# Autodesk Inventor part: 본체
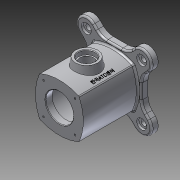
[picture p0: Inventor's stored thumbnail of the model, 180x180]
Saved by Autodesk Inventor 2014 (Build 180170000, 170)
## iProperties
Created: 2016-05
Part Number: 본체
Material: 알루미늄 6061
Document SubType Name: Modeling
Designer: Administrator
Density: 2.71 g/cm^3
Appearance: 알루미늄 - 평지
Mass: 1114.31 g
Surface Area: 867.27 cm^2
Volume: 411.184 cm^3
Author: Administrator
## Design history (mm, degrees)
sketch "스케치2"
  geometry: L1 (-35.355, -35.355)-(35.355, -35.355); L2 (35.355, -35.355)-(35.355, 35.355); L3 (35.355, 35.355)-(-35.355, 35.355); L4 (-35.355, 35.355)-(-35.355, -35.355); L5 (-35.355, -35.355)-(35.355, 35.355); L6 (35.355, -35.355)-(-35.355, 35.355); L7 (0, -60.2)-(0, 60.2) reference; A1 r 85.579 centre (42.579, 0) between (-35.355, 35.355) and (-35.355, -35.355); A2 r 85.579 centre (0, 42.579) between (-35.355, -35.355) and (35.355, -35.355); A3 r 85.579 centre (-42.579, 0) between (35.355, -35.355) and (35.355, 35.355); A4 r 85.579 centre (0, -42.579) between (35.355, 35.355) and (-35.355, 35.355); 5 further points
  constraints: 12 end point, 12 point on circle, 4 centre point, 2 equal radius, 2 midpoint, 2 parallel, 1 horizontal, 1 perpendicular
  dimensions: "d4" = 100 distance of L1.end L3.end; "d5" = 45 deg angle of L7 L6; "d6" = 86 distance of point (0, -43) point (0, 43); "d7" = 86 distance of point (43, 0) point (-43, 0)
extrude "돌출1" new body sketch "스케치2" distance "d8" = 55; taper "d9" = 0 deg
sketch "스케치3"
  geometry: 2 further points
  constraints: 1 coincident
hole "구멍1" sketch "스케치3" at (0, 0) diameter "d10" = 50; stored, may be unused: countersink angle "d14" = 90 deg, drill point angle "d16" = 118 deg; dims "d11" = 6, "d12" = 70, "d13" = 43, "d15" = 8
sketch "스케치5"
  geometry: L1 (49, 55)-(49, 39); L2 (49, 39)-(71.821, 39); L3 (71.821, 39)-(69, 55); L4 (69, 55)-(49, 55); L5 (-22, 0)-(132, 0) reference; L6 (0, 43)-(110, 43) reference; L7 (0, -35.355)-(0, 35.355) reference; 1 further point
  constraints: 8 end point, 1 parallel, 1 perpendicular, 1 vertical
  dimensions: "d22" = 39 distance between parallel lines of L5 L2; "d23" = 55 distance between parallel lines of L5 L4; "d24" = 100 deg angle of L6 L3; "d25" = 49 distance between parallel lines of L7 L1; "d26" = 20 distance of L3.end L1.start
revolve "회전1" sketch "스케치5" stored, may be unused: angle "d27" = 90 deg
hole "구멍2" diameter "d30" = 25; stored, may be unused: countersink angle "d34" = 90 deg, drill point angle "d36" = 0 deg; dims "d28" = 10, "d29" = 10, "d31" = 6, "d32" = 30, "d33" = 8, "d35" = 8
sketch "스케치6" dims "d43" = 70
  geometry: L1 (0, 42.579)-(-49, 42.579); L2 (-49, 42.579)-(-49, 91.579); L3 (-49, 91.579)-(0, 91.579); L4 (0, 91.579)-(0, 42.579); L5 (0, 42.579)-(-67.637, 110.215); L6 (-74.953, 92.076)-(-49.497, 117.532); L7 (-49.497, 117.532)-(-23.544, 91.579); L8 (-23.544, 91.579)-(-49, 66.123); L9 (-49, 66.123)-(-74.953, 92.076); A1 r 25 centre (0, 42.579) between (0, 67.579) and (-25, 42.579) reference; 2 further points
  constraints: 18 end point, 5 point on line, 4 parallel, 3 perpendicular, 2 point on circle, 1 coincident, 1 horizontal, 3 other
  dimensions: "d37" = 45 deg angle of L4 L5; "d38" = 98 diameter of L2 L4; "d40" = 36 distance of L6.start L6.end; "d41" = 18 distance between parallel lines of L5 L7; "d44" = 18 distance from line of L6 point (-49.497, 92.076)
extrude "돌출4" join sketch "스케치6" distance "d47" = 12; taper "d48" = 0 deg
fillet "모깎기1"
fillet "모깎기2" dims "d49" = 25
hole "구멍3" diameter "d52" = 10; stored, may be unused: countersink angle "d56" = 90 deg, drill point angle "d58" = 0 deg; dims "d50" = 10, "d51" = 10, "d53" = 6, "d54" = 18, "d55" = 4, "d57" = 8
sketch "스케치7" dims "d60" = 40
  geometry: L1 (-30.866, 13.744)-(-36.77, 19.647) reference; L2 (0, -42.579)-(-49.497, 6.919); C1 r 25 at (0, -42.579) reference; A1 r 18 centre (-49.497, 6.919) between (-36.77, 19.647) and (-62.225, -5.809) reference; 1 further point
  constraints: 2 end point, 1 coincident, 1 parallel, 1 point on line, 3 other
hole "구멍4" sketch "스케치7" at (-28.284, -14.294) diameter "d61" = 3.242; stored, may be unused: countersink angle "d65" = 90 deg, drill point angle "d67" = 118 deg; dims "d62" = 7, "d63" = 18, "d64" = 4, "d66" = 10
sketch "스케치8"
  geometry: L1 (0, 0)-(-28.284, 28.284); L2 (0, -94.496)-(0, 94.496) reference; C1 r 25 at (0, 0) reference
  constraints: 2 end point
  dimensions: "d68" = 40 distance of L1.start L1.end; "d69" = 45 deg angle of L2 L1
hole "구멍5" sketch "스케치8" at (-28.284, 28.284) diameter "d70" = 3.242; stored, may be unused: countersink angle "d74" = 90 deg, drill point angle "d76" = 118 deg; dims "d71" = 7, "d72" = 18, "d73" = 4, "d75" = 10
chamfer "모따기1" distance "d80" = 1; stored, may be unused: second distance "d81" = 2, angle "d82" = 45 deg
fillet "모깎기3" dims "d83" = 3
fillet "모깎기4" dims "d84" = 3
fillet "모깎기5" dims "d85" = 3
fillet "모깎기6" dims "d86" = 3
node "작업 평면3"
sketch "스케치9"
  geometry: L1 (0, -22)-(0, 132) reference; L2 (34.285, 0)-(-34.285, 0) reference; 2 further points
  constraints: 1 other
  dimensions: "d88" = 29 distance from line of point (29, 49) L1; "d89" = 49 distance from line of L2 point (29, 49)
feature "엠보싱1" sketch "스케치9" dims "d4" = 100, "d5" = 45 deg, "d6" = 86, "d7" = 86, "d90" = 0.5, "d91" = 0
chamfer "모따기2" distance "d92" = 1; stored, may be unused: second distance "d93" = 2, angle "d94" = 45 deg
node "솔리드1"
mirror "대칭1"
mirror "대칭2"
mirror "대칭4"
pattern_circular "원형 패턴1" dims angle "d78" = 360 deg
other parameters: "d87" = 102.25
